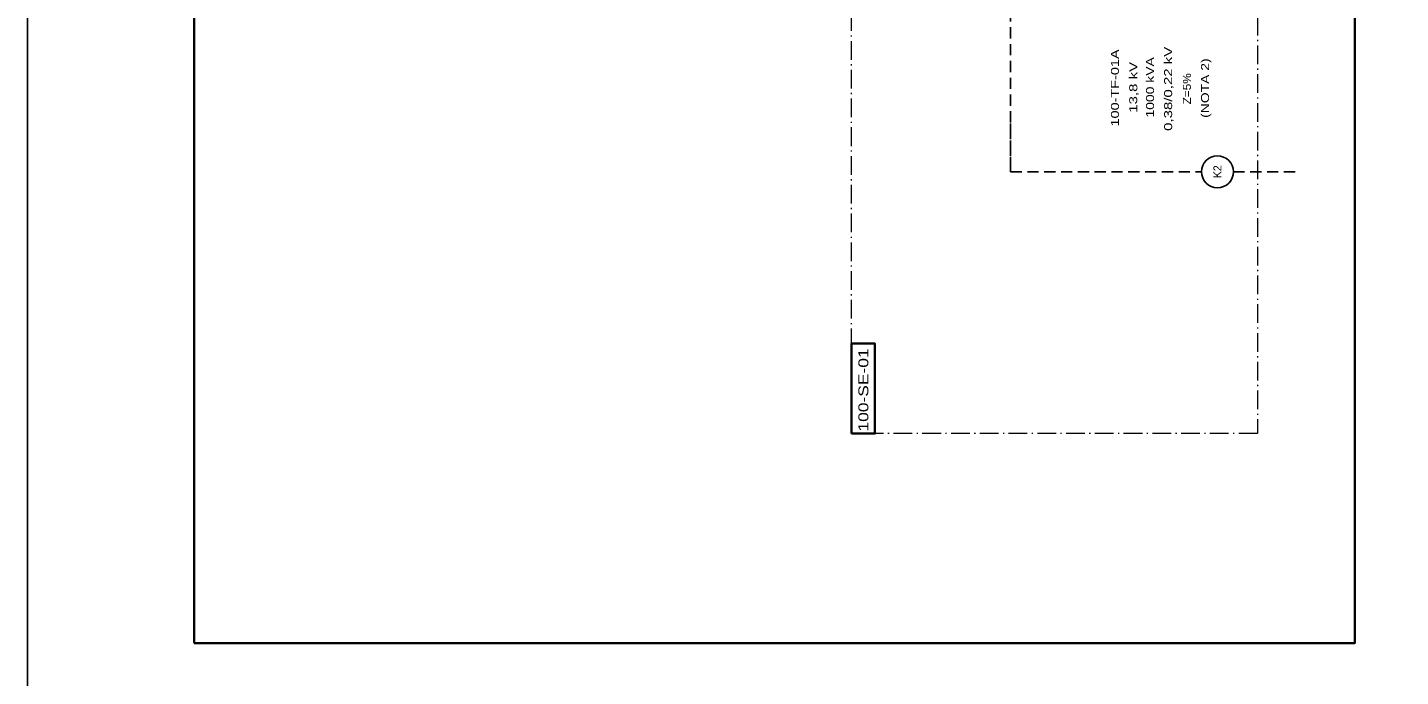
# Model space of a CAD drawing. Extents: x -4160 to -2690, y -474 to 714.
# Drawn here: x -3529.8 to -3323.9, y 422.5 to 519.8 of the extents above; entities that cross this region are included whole.
import ezdxf
from ezdxf.enums import TextEntityAlignment as Align

# ---------------------------------------------------------------- set-up
doc = ezdxf.new("R2010")
doc.units = 0
doc.header["$LTSCALE"] = 0.56
doc.linetypes.add('DOT_DASHED', pattern=[7.7, 5, -1.2, 0.3, -1.2])
doc.linetypes.add('MEDIUM_DASHED', pattern=[4.5, 3, -1.5])
doc.layers.add('5', color=7, linetype='Continuous', lineweight=35)

msp = doc.modelspace()

# ---------------------------------------------------------------- linework, layer by layer
at = {"layer": '5', "linetype": 'MEDIUM_DASHED', "lineweight": 25}
msp.add_line((-3348.9632, 498.1858), (-3339.0046, 498.1858), dxfattribs=at)
msp.add_line((-3348.9632, 498.1858), (-3339.0046, 498.1858), dxfattribs=at)
at = {"layer": '5', "lineweight": 25}
msp.add_lwpolyline([(-3319.7642, 417.48), (-3529.7642, 417.48), (-3529.7642, 714.48), (-3319.7642, 714.48)], close=True, dxfattribs=at)
at = {"layer": '5'}
for points in [[(-3504.7642, 427.48), (-3504.7642, 680.48), (-3330.7642, 680.48), (-3330.7642, 427.48)], [(-3406.2365, 458.917), (-3406.2365, 472.4198), (-3402.7058, 472.4198), (-3402.7058, 458.917)]]:
    msp.add_lwpolyline(points, close=True, dxfattribs=at)
at = {"layer": '5', "linetype": 'DOT_DASHED', "lineweight": 13}
msp.add_lwpolyline([(-3473.5534, 659.4019), (-3345.3718, 659.4019), (-3345.3718, 458.917), (-3406.2365, 458.917), (-3406.2365, 529.5479), (-3473.5534, 529.5479)], close=True, dxfattribs=at)
at = {"layer": '5', "linetype": 'MEDIUM_DASHED', "lineweight": 25}
for points in [[(-3382.3712, 527.4033), (-3382.3712, 498.1858), (-3353.7607, 498.1858)], [(-3382.3712, 505.3881), (-3382.3712, 498.1858), (-3353.7607, 498.1858)]]:
    msp.add_lwpolyline(points, dxfattribs=at)
at = {"layer": '5', "lineweight": 25}
msp.add_circle((-3351.362, 498.1765), 2.3988, dxfattribs=at)
msp.add_circle((-3351.362, 498.1765), 2.3988, dxfattribs=at)

# ---------------------------------------------------------------- texts
at = {"layer": '5'}
for s, height, width, p in [('0,38/0,22 kV', 1.2, 1.4, (-3358.1518, 510.6103)), ('0,38/0,22 kV', 1.2, 1.4, (-3358.1518, 510.6103)), ('100-TF-01A', 1.2, 1.35, (-3366.1261, 510.7413)), ('1000 kVA', 1.2, 1.3, (-3360.8657, 510.8289)), ('1000 kVA', 1.2, 1.3, (-3360.8657, 510.8289)), ('(NOTA 2)', 1.2, 1.3, (-3352.617, 510.7156)), ('13,8 kV', 1.2, 1.4, (-3363.3842, 510.8336)), ('13,8 kV', 1.2, 1.4, (-3363.3842, 510.8336)), ('Z=5%', 1.2, 1.1, (-3355.3331, 510.6103)), ('Z=5%', 1.2, 1.1, (-3355.3331, 510.6103)), ('100-SE-01', 1.5, 1.3, (-3403.6924, 465.4533))]:
    msp.add_text(s, height=height, rotation=90, dxfattribs=dict(at, width=width)).set_placement(p, align=Align.CENTER)
msp.add_text('K2', height=1.2, rotation=90, dxfattribs=at).set_placement((-3350.762, 498.1765), align=Align.CENTER)
msp.add_text('K2', height=1.2, rotation=90, dxfattribs=at).set_placement((-3350.762, 498.1765), align=Align.CENTER)

doc.saveas('drawing.dxf')
